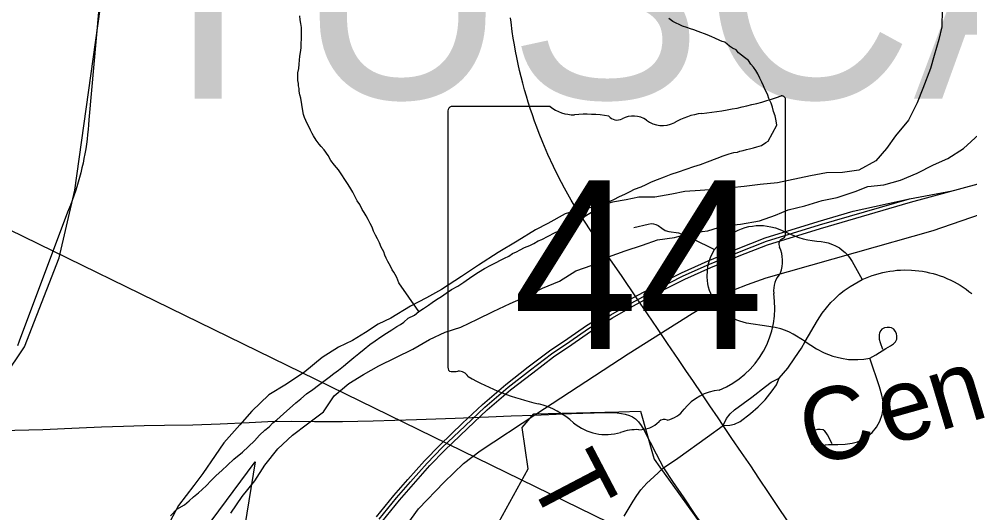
# Model space of a CAD drawing. Extents: x -6.1 to 38, y -7.7 to 22.
# Drawn here: x 5.97 to 6.713, y 18.842 to 19.227 of the extents above; entities that cross this region are included whole.
import ezdxf

# ---------------------------------------------------------------- set-up
doc = ezdxf.new("R2010")
doc.units = 0
for name, color, linetype in [('GM_X_City_Street', 7, 'Continuous'), ('GM_X_Corporation', 7, 'Continuous'), ('GM_X_County_Road', 7, 'Continuous'), ('GM_X_Major_River', 7, 'Continuous'), ('GM_X_Minor_River', 7, 'Continuous'), ('GM_X_Rail_Line', 7, 'Continuous'), ('GM_X_Rail_Line_Text', 7, 'Continuous'), ('GM_X_State_Location', 7, 'Continuous'), ('GM_X_State_Route', 7, 'Continuous'), ('GM_X_State_Shield', 7, 'Continuous'), ('GM_X_Township_Road', 7, 'Continuous'), ('GM_X_Township_Road_Text', 7, 'Continuous'), ('GM_X_Township_Text', 7, 'Continuous'), ('SH_Text', 7, 'Continuous')]:
    doc.layers.add(name, color=color, linetype=linetype)

msp = doc.modelspace()

# ---------------------------------------------------------------- linework, layer by layer
at = {"layer": 'GM_X_City_Street'}
for points in [[(6.45065, 19.06454), (6.46175, 19.06721), (6.46394, 19.06761), (6.4658, 19.06745), (6.46774, 19.06697), (6.4696, 19.06623), (6.47245, 19.064), (6.47502, 19.06227), (6.47785, 19.0613), (6.48538, 19.06042), (6.48829, 19.05944), (6.49598, 19.05588), (6.51351, 19.04728)], [(6.58441, 18.97548), (6.57768, 18.97978), (6.57498, 18.98132), (6.57219, 18.98271), (6.5691, 18.98403), (6.56543, 18.98532), (6.5609, 18.9864), (6.55596, 18.98716), (6.53845, 18.9899), (6.53585, 18.9905), (6.53334, 18.99127), (6.53087, 18.99222), (6.52846, 18.99335), (6.52562, 18.99497), (6.52339, 18.99645), (6.5213, 18.99809), (6.51937, 18.99985), (6.51752, 19.00176), (6.51581, 19.00378), (6.51425, 19.00593), (6.51288, 19.00817), (6.5116, 19.01051), (6.51056, 19.01293), (6.50966, 19.01541), (6.5089, 19.01796), (6.50839, 19.02054), (6.50801, 19.02317), (6.50781, 19.0258), (6.50801, 19.03109), (6.50839, 19.03371), (6.50891, 19.03629), (6.50967, 19.03884), (6.51077, 19.04177), (6.51351, 19.04728), (6.51746, 19.05175), (6.51946, 19.05389), (6.52154, 19.05587), (6.52439, 19.05814), (6.5268, 19.05976), (6.52936, 19.06121), (6.53197, 19.06249), (6.53467, 19.06358), (6.53742, 19.06448), (6.54026, 19.06519), (6.54311, 19.06569), (6.546, 19.06599), (6.54894, 19.0661), (6.55183, 19.06599), (6.55471, 19.06568), (6.5576, 19.06518), (6.56111, 19.06426), (6.56452, 19.06306), (6.57281, 19.05939), (6.57613, 19.05803), (6.57949, 19.05683), (6.5829, 19.05581), (6.58636, 19.05498), (6.58987, 19.05433), (6.59342, 19.05385), (6.59692, 19.05355), (6.59967, 19.05313), (6.60242, 19.05247), (6.60559, 19.05138), (6.60815, 19.05022), (6.61109, 19.04854), (6.61336, 19.0469), (6.61554, 19.04507), (6.61748, 19.04307), (6.61961, 19.04045), (6.62118, 19.0381), (6.62886, 19.02384)], [(6.5641, 18.94691), (6.57077, 18.9547), (6.57636, 18.96262), (6.58142, 18.97029), (6.58441, 18.97548), (6.59397, 18.99202), (6.59767, 18.99755), (6.60101, 19.00176), (6.60449, 19.0059), (6.60727, 19.00868), (6.6111, 19.01237), (6.61481, 19.01534), (6.61708, 19.017), (6.61945, 19.01858), (6.62886, 19.02384), (6.63413, 19.02612), (6.63679, 19.02708), (6.63948, 19.02794), (6.64223, 19.02871), (6.64503, 19.02939), (6.64758, 19.02993), (6.65038, 19.03041), (6.65323, 19.0308), (6.65607, 19.03109), (6.65891, 19.03128), (6.66176, 19.03137), (6.66744, 19.03126), (6.67023, 19.03105), (6.67308, 19.03075), (6.67592, 19.03035), (6.67872, 19.02984), (6.68146, 19.02925), (6.68426, 19.02855), (6.68696, 19.02776), (6.68966, 19.02687), (6.69236, 19.02589), (6.69496, 19.02483), (6.69814, 19.0234), (6.7006, 19.02215), (6.70307, 19.02082), (6.70543, 19.0194), (6.7078, 19.01791), (6.71008, 19.01633), (6.7123, 19.01467), (6.71448, 19.01294)], [(6.58441, 18.97548), (6.59321, 18.96968), (6.59925, 18.96652), (6.60602, 18.96392), (6.61263, 18.96234), (6.61824, 18.96148), (6.62541, 18.96139), (6.63021, 18.96179), (6.63484, 18.96259), (6.63946, 18.96509), (6.64723, 18.96999), (6.65106, 18.97211), (6.65341, 18.97358), (6.65495, 18.97513), (6.65582, 18.97735), (6.656, 18.97969), (6.65563, 18.9817), (6.65476, 18.98363), (6.6536, 18.98508), (6.65186, 18.98604), (6.65031, 18.98644), (6.64828, 18.98653), (6.6462, 18.98608), (6.64423, 18.98517), (6.64332, 18.98411), (6.64239, 18.98238), (6.6421, 18.98061), (6.64225, 18.97743), (6.64301, 18.97469), (6.64473, 18.96953)], [(6.60531, 18.89566), (6.60175, 18.90269), (6.60085, 18.9041), (6.5996, 18.90546), (6.59829, 18.90637), (6.59618, 18.90676), (6.59404, 18.90666), (6.59216, 18.90611), (6.59065, 18.90492), (6.58922, 18.90328), (6.58843, 18.90115), (6.58836, 18.89931), (6.58868, 18.89731), (6.58949, 18.89565), (6.59074, 18.89453), (6.59238, 18.89361), (6.59422, 18.89317), (6.59801, 18.89386), (6.60031, 18.8947), (6.60259, 18.89508), (6.60993, 18.89496), (6.61563, 18.89521), (6.62103, 18.89596), (6.62534, 18.89715), (6.62912, 18.89887), (6.633, 18.90125), (6.63667, 18.90438), (6.64012, 18.90858), (6.64271, 18.91322), (6.64454, 18.9184), (6.6453, 18.92304), (6.6454, 18.92649), (6.64498, 18.93005), (6.64411, 18.93361), (6.64238, 18.93998), (6.63484, 18.96259)], [(6.52032, 18.90992), (6.52549, 18.91002), (6.52919, 18.911), (6.53348, 18.91304), (6.54167, 18.91924), (6.54765, 18.92457), (6.55311, 18.92998), (6.55869, 18.93703), (6.56195, 18.94165), (6.5641, 18.94691)], [(6.52032, 18.90992), (6.52286, 18.91528), (6.52568, 18.91908), (6.52919, 18.92201), (6.54256, 18.93212), (6.55324, 18.94024), (6.55777, 18.9436), (6.5641, 18.94691)]]:
    msp.add_lwpolyline(points, dxfattribs=at)
at = {"layer": 'GM_X_Corporation'}
for points in [[(6.05133, 19.44458), (6.02484, 19.14859), (6.0246, 19.1448), (6.02431, 19.14102), (6.02393, 19.13724), (6.0235, 19.13348), (6.02298, 19.12971), (6.02241, 19.12595), (6.02179, 19.12221), (6.02108, 19.11848), (6.02032, 19.11476), (6.01951, 19.11107), (6.01861, 19.10737), (6.01766, 19.1037), (6.01662, 19.10005), (6.01552, 19.0964), (6.01439, 19.09279), (6.0132, 19.08919), (6.01192, 19.08562), (6.01059, 19.08206), (6.00831, 19.0765), (5.9704, 18.97578), (5.96908, 18.97223)], [(5.93858, 18.81896), (5.97794, 18.81995), (6.34227, 18.82912), (6.36798, 18.87608), (6.36335, 18.90837), (6.37231, 18.91892), (6.43888, 18.92061), (6.4557, 18.92104), (6.46568, 18.88615), (6.46644, 18.88349), (6.47084, 18.87738), (6.48566, 18.85674), (6.62273, 18.66603), (6.658, 18.6169), (6.66307, 18.60986), (6.66889, 18.60176), (6.66908, 18.60068), (6.67187, 18.58221), (6.67352, 18.57001), (6.68778, 18.46834), (6.69665, 18.40504), (7.00648, 18.41584)], [(6.08072, 18.78188), (6.15483, 18.88149), (6.13494, 18.75951)]]:
    msp.add_lwpolyline(points, dxfattribs=at)
at = {"layer": 'GM_X_County_Road'}
for points in [[(6.47378, 18.87668), (6.48491, 18.88443), (6.50803, 18.90105), (6.52032, 18.90992)], [(6.44301, 18.83916), (6.45004, 18.85081), (6.45274, 18.85512), (6.45587, 18.85952), (6.46078, 18.86476), (6.4661, 18.86975), (6.47378, 18.87668)]]:
    msp.add_lwpolyline(points, dxfattribs=at)
at = {"layer": 'GM_X_Major_River'}
for points in [[(6.69132, 19.23493), (6.69103, 19.22128), (6.68883, 19.21141), (6.68513, 19.19887), (6.68217, 19.18861), (6.67622, 19.17303), (6.67175, 19.162), (6.66503, 19.1483), (6.6549, 19.1361), (6.64778, 19.1262), (6.63952, 19.11666), (6.62633, 19.10937), (6.61349, 19.10739), (6.60101, 19.10731), (6.58854, 19.10495), (6.56286, 19.09947), (6.54925, 19.09825), (6.53679, 19.09665), (6.52658, 19.09544), (6.51335, 19.09422), (6.50239, 19.09339), (6.49029, 19.09255), (6.48009, 19.09059), (6.46687, 19.08823), (6.45439, 19.08814), (6.44457, 19.08618), (6.43399, 19.08422), (6.41965, 19.08033), (6.40718, 19.07835), (6.39699, 19.07525), (6.38343, 19.06758), (6.37362, 19.06259), (6.35931, 19.05377), (6.34462, 19.04495), (6.32918, 19.03499), (6.316, 19.02618), (6.30018, 19.01622), (6.2885, 19.0097), (6.27606, 19.00317), (6.26061, 18.99359), (6.25081, 18.98897), (6.24102, 18.98246), (6.23085, 18.97633), (6.21992, 18.97095), (6.20711, 18.9629), (6.19357, 18.95181), (6.17926, 18.94224), (6.16532, 18.9338), (6.15217, 18.9212), (6.14278, 18.91052), (6.13039, 18.89641), (6.12365, 18.88651), (6.11391, 18.87241), (6.10679, 18.86288), (6.09478, 18.84726), (6.08843, 18.83508)], [(6.13567, 18.84146), (6.14466, 18.85441), (6.15441, 18.86661), (6.16228, 18.8788), (6.1724, 18.89176), (6.18406, 18.90245), (6.19572, 18.91125), (6.20814, 18.92043), (6.21638, 18.933), (6.22804, 18.94256), (6.23934, 18.94984), (6.2514, 18.95636), (6.27779, 18.96943), (6.29098, 18.9771), (6.30304, 18.98287), (6.3155, 18.98674), (6.32832, 18.99289), (6.34076, 18.99904), (6.35395, 19.0052), (6.3664, 19.01059), (6.37922, 19.01712), (6.39242, 19.02252), (6.40522, 19.03056), (6.41805, 19.0352), (6.43087, 19.04173), (6.4437, 19.04636), (6.45728, 19.05062), (6.46898, 19.05487), (6.4822, 19.05685), (6.49504, 19.06035), (6.50827, 19.06196), (6.52072, 19.06583), (6.53395, 19.06705), (6.54868, 19.0698), (6.56114, 19.07406), (6.57094, 19.07829), (6.58416, 19.08141), (6.59775, 19.08567), (6.60946, 19.08803), (6.62342, 19.09267), (6.63323, 19.09652), (6.6457, 19.09774), (6.65891, 19.10162), (6.67173, 19.10701), (6.68455, 19.11354), (6.69586, 19.11855), (6.70791, 19.12621), (6.71995, 19.13728)], [(6.52043, 19.12057), (6.52496, 19.12217), (6.52875, 19.123), (6.5314, 19.12343), (6.53328, 19.12422), (6.53593, 19.12465), (6.53858, 19.12546), (6.54085, 19.12588), (6.54387, 19.12669), (6.54651, 19.1275), (6.55029, 19.12871), (6.55367, 19.13105), (6.55555, 19.13185)], [(6.09957, 18.84797), (6.10332, 18.85108), (6.10668, 18.85418), (6.11042, 18.85729), (6.11341, 18.86001), (6.11677, 18.86311), (6.12013, 18.86659), (6.12423, 18.87085), (6.12872, 18.87473), (6.1332, 18.87899), (6.13805, 18.88364), (6.14479, 18.88909), (6.14965, 18.89336), (6.15413, 18.898), (6.15823, 18.90226), (6.16234, 18.90614), (6.16571, 18.90886), (6.16869, 18.91196), (6.17168, 18.91429), (6.1743, 18.91662), (6.17692, 18.91895), (6.18664, 18.92749), (6.19038, 18.9306), (6.19487, 18.93448), (6.19974, 18.93799), (6.20424, 18.94149), (6.20836, 18.94461), (6.21248, 18.94772), (6.21623, 18.95046), (6.21998, 18.95319), (6.22372, 18.95629), (6.22709, 18.95902), (6.23196, 18.96291), (6.2357, 18.96602), (6.23982, 18.96951), (6.24431, 18.97302), (6.24843, 18.97613), (6.25293, 18.97926), (6.25744, 18.982), (6.26157, 18.98473), (6.26533, 18.98708), (6.26834, 18.98866), (6.27096, 18.99061), (6.27432, 18.99371), (6.27922, 18.99608), (6.28259, 18.9988), (6.28634, 19.00115), (6.29009, 19.00388), (6.2931, 19.00583), (6.29647, 19.00818), (6.30023, 19.01053), (6.30398, 19.01326), (6.30811, 19.01599), (6.31299, 19.01874), (6.31787, 19.02187), (6.32387, 19.02616), (6.32913, 19.02968), (6.33402, 19.03243), (6.3389, 19.03518), (6.34305, 19.03715), (6.34643, 19.03912), (6.34944, 19.04069), (6.35283, 19.04227), (6.35583, 19.04423), (6.35885, 19.04542), (6.36186, 19.047), (6.36524, 19.04896), (6.36939, 19.05055), (6.3724, 19.05213), (6.37578, 19.05409), (6.3788, 19.05529), (6.38858, 19.0604), (6.39197, 19.06199), (6.39498, 19.06356), (6.39762, 19.06475), (6.39988, 19.06593), (6.40364, 19.0679), (6.4074, 19.07025), (6.41153, 19.07299), (6.41604, 19.07573), (6.42092, 19.07848), (6.42581, 19.08123), (6.43031, 19.08435), (6.43483, 19.08633), (6.43935, 19.0887), (6.44349, 19.09067), (6.44763, 19.09265), (6.45102, 19.09461), (6.45631, 19.09622), (6.46007, 19.09819), (6.46421, 19.10017), (6.46911, 19.10216), (6.47439, 19.10415), (6.47968, 19.10615), (6.48534, 19.10815), (6.49138, 19.11016), (6.49742, 19.11217), (6.5027, 19.11379), (6.50799, 19.11578), (6.51553, 19.11858), (6.52043, 19.12057)], [(6.08871, 18.83941), (6.09356, 18.84444), (6.09957, 18.84797)]]:
    msp.add_lwpolyline(points, dxfattribs=at)
at = {"layer": 'GM_X_Minor_River'}
for points in [[(6.28259, 18.9988), (6.26699, 19.02134), (6.2654, 19.02549), (6.26422, 19.02775), (6.26304, 19.02963), (6.26187, 19.03151), (6.26069, 19.03377), (6.25951, 19.03604), (6.25834, 19.03791), (6.25715, 19.04055), (6.25597, 19.04282), (6.25517, 19.04546), (6.2532, 19.04923), (6.252, 19.05263), (6.25043, 19.05565), (6.24885, 19.05866), (6.24728, 19.06167), (6.24608, 19.06469), (6.24451, 19.06771), (6.24294, 19.07072), (6.24136, 19.07374), (6.2398, 19.07637), (6.23824, 19.07862), (6.23665, 19.0824), (6.23432, 19.0854), (6.23275, 19.08841), (6.23116, 19.09219), (6.22881, 19.09595), (6.22686, 19.09896), (6.22491, 19.10196), (6.22256, 19.10572), (6.21983, 19.10948), (6.21673, 19.11322), (6.214, 19.11698), (6.21166, 19.12074), (6.20854, 19.12525), (6.20621, 19.12787), (6.20466, 19.12974), (6.20232, 19.13274), (6.20036, 19.13613), (6.19919, 19.13801), (6.198, 19.14065), (6.19683, 19.14291), (6.19565, 19.14517), (6.19445, 19.14819), (6.19327, 19.15045), (6.19247, 19.15272), (6.19204, 19.15575), (6.19034, 19.16561), (6.18954, 19.16826), (6.18911, 19.17091), (6.18907, 19.17319), (6.18865, 19.17509), (6.18862, 19.17699), (6.1882, 19.17926), (6.18813, 19.18306), (6.18809, 19.18534), (6.18879, 19.18878), (6.18911, 19.19221), (6.18943, 19.19526), (6.18975, 19.1983), (6.19008, 19.20135), (6.19078, 19.20479), (6.19072, 19.20821), (6.19103, 19.21202), (6.19097, 19.21506), (6.19092, 19.2181), (6.19087, 19.22076), (6.19044, 19.22379), (6.19, 19.22683), (6.18957, 19.22986)], [(6.55555, 19.13185), (6.56216, 19.14451), (6.56172, 19.14793), (6.56089, 19.15172), (6.55969, 19.15512), (6.55887, 19.15853), (6.55768, 19.16155), (6.55609, 19.16532), (6.55528, 19.16797), (6.55411, 19.17023), (6.55292, 19.17249), (6.55174, 19.17513), (6.55054, 19.17815), (6.54897, 19.18116), (6.54739, 19.18456), (6.54582, 19.18719), (6.54388, 19.18982), (6.54194, 19.19207), (6.53998, 19.19508), (6.53691, 19.1973), (6.5346, 19.19916), (6.53228, 19.20102), (6.53034, 19.20327), (6.52766, 19.20474), (6.52535, 19.20622), (6.52343, 19.20771), (6.5215, 19.20919), (6.51959, 19.20992), (6.51768, 19.21065), (6.51385, 19.21248), (6.51155, 19.21358), (6.50964, 19.2143), (6.50772, 19.21503), (6.50084, 19.21757), (6.4974, 19.21903), (6.49473, 19.21974), (6.49205, 19.22083), (6.48861, 19.22191), (6.48593, 19.22301), (6.48364, 19.22411), (6.48095, 19.22558), (6.47787, 19.22781)]]:
    msp.add_lwpolyline(points, dxfattribs=at)
at = {"layer": 'GM_X_Rail_Line'}
msp.add_line((6.6659, 19.08696), (6.69916, 19.09305), dxfattribs=at)
for points in [[(4.164, 17.08105), (4.22288, 17.11422), (4.28514, 17.16362), (4.3773, 17.2385), (4.46626, 17.31066), (4.52352, 17.37506), (4.57967, 17.45347), (4.643, 17.54537), (5.03778, 18.11028), (5.18813, 18.32179), (5.2285, 18.37664), (5.2671, 18.40903), (5.31379, 18.44323), (5.44065, 18.5342), (5.77322, 18.77518), (5.85708, 18.83753), (5.92575, 18.89871), (5.97472, 18.97128), (6.00159, 19.04095), (6.01392, 19.09362), (6.04108, 19.2873)], [(6.25392, 18.83493), (6.26743, 18.8515), (6.27836, 18.86407), (6.29129, 18.87852), (6.30292, 18.89062), (6.32066, 18.90754), (6.33605, 18.92199), (6.35427, 18.93762), (6.37154, 18.95113), (6.38787, 18.96347), (6.40209, 18.97322), (6.41678, 18.98321), (6.43393, 18.9939), (6.44979, 19.00307), (6.46847, 19.01317), (6.49033, 19.0241), (6.51077, 19.03327), (6.53275, 19.04231), (6.55501, 19.05111), (6.59625, 19.06383), (6.66667, 19.08423), (6.7474, 19.10615)], [(6.24942, 18.8384), (6.26307, 18.85514), (6.27408, 18.86781), (6.2871, 18.88237), (6.29889, 18.89464), (6.31674, 18.91166), (6.33224, 18.92621), (6.35065, 18.94201), (6.36806, 18.95563), (6.38453, 18.96807), (6.39887, 18.9779), (6.41366, 18.98796), (6.43099, 18.99876), (6.447, 19.00802), (6.46584, 19.0182), (6.48788, 19.02923), (6.50852, 19.03848), (6.53061, 19.04757), (6.55312, 19.05646), (6.59462, 19.06926), (6.6219, 19.07717), (6.6659, 19.08696)], [(6.25167, 18.83667), (6.26525, 18.85332), (6.27622, 18.86594), (6.28919, 18.88045), (6.3009, 18.89263), (6.3187, 18.9096), (6.33415, 18.9241), (6.35246, 18.93981), (6.3698, 18.95338), (6.3862, 18.96577), (6.40048, 18.97556), (6.41522, 18.98559), (6.43246, 18.99633), (6.4484, 19.00554), (6.46716, 19.01569), (6.48911, 19.02666), (6.50965, 19.03587), (6.53168, 19.04494), (6.55407, 19.05378), (6.59544, 19.06655), (6.6659, 19.08696)], [(6.26379, 18.81929), (6.28238, 18.84483), (6.30238, 18.8657), (6.31752, 18.88007), (6.33043, 18.89016), (6.37391, 18.9187), (6.44622, 18.96597), (6.49602, 18.99732), (6.51776, 19.01042), (6.52873, 19.01576), (6.53931, 19.02013), (6.55387, 19.02528), (6.62375, 19.04498), (6.68442, 19.06216), (6.75906, 19.08788)]]:
    msp.add_lwpolyline(points, dxfattribs=at)
at = {"layer": 'GM_X_State_Route'}
msp.add_lwpolyline([(6.57235, 18.83268), (6.56515, 18.84345), (6.55615, 18.85688), (6.54826, 18.86868), (6.5418, 18.87832), (6.53461, 18.88889), (6.52718, 18.89984), (6.52032, 18.90992), (6.51633, 18.91579), (6.5099, 18.92526), (6.50363, 18.93448), (6.49703, 18.94421), (6.49109, 18.95295), (6.48536, 18.96138), (6.47686, 18.97388), (6.46891, 18.98558), (6.46112, 18.99706), (6.45262, 19.00956), (6.44083, 19.02692), (6.42695, 19.0472), (6.41926, 19.0583), (6.413, 19.06786), (6.40685, 19.07742), (6.40168, 19.08599), (6.3963, 19.09533), (6.39168, 19.10401), (6.38773, 19.11213), (6.38333, 19.12169), (6.37949, 19.13081), (6.37656, 19.13801), (6.37476, 19.14282), (6.37296, 19.14766), (6.37126, 19.15252), (6.36965, 19.15741), (6.36809, 19.16232), (6.36658, 19.16725), (6.36515, 19.1722), (6.36383, 19.17718), (6.36256, 19.18216), (6.36133, 19.18716), (6.36019, 19.1922), (6.35915, 19.19724), (6.35811, 19.20229), (6.35721, 19.20735), (6.35636, 19.21243), (6.35561, 19.21752), (6.35462, 19.22505), (6.35419, 19.22841)], dxfattribs=at)
at = {"layer": 'GM_X_State_Shield'}
for p, q in [((6.56901, 19.05927), (6.56901, 19.16396)), ((6.30535, 19.15555), (6.30535, 18.95543)), ((6.38516, 19.159), (6.30794, 19.159)), ((6.56899, 19.0593), (6.56901, 19.05927))]:
    msp.add_line(p, q, dxfattribs=at)
for centre, radius, start, end in [((6.47509, 19.43183), 0.27962, 275.84447, 288.90645), ((6.56609, 19.16439), 0.00294, 351.86209, 97.738), ((6.30837, 19.15598), 0.00305, 98.1301, 188.1301), ((6.40355, 19.18223), 0.02963, 231.61951, 271.11188), ((6.41337, 19.04665), 0.10636, 80.48669, 94.98827), ((6.43752, 19.15702), 0.00855, 219.79206, 297.10237), ((6.45007, 19.13389), 0.01777, 54.46668, 119.14113), ((6.473, 19.16561), 0.02138, 233.85621, 294.82819), ((6.51076, 19.09787), 0.05625, 97.34618, 120.76885), ((6.56588, 19.05887), 0.00314, 289.60381, 7.73413), ((6.56833, 19.05159), 0.00454, 107.94398, 210.33697), ((6.53944, 19.03835), 0.02727, 340.03296, 23.64957), ((6.57953, 19.01546), 0.01984, 136.8065, 186.92959), ((6.49075, 19.00214), 0.06994, 292.30889, 8.98584), ((6.30839, 18.95499), 0.00308, 171.95839, 258.30661), ((6.30886, 18.97547), 0.02352, 267.33899, 280.60386), ((6.31367, 18.94389), 0.00848, 29.74838, 93.27175), ((6.42073, 19.12369), 0.20192, 240.41292, 257.1985), ((6.52024, 18.89925), 0.0383, 94.40312, 142.57675), ((6.36053, 18.86553), 0.06318, 47.18416, 75.83597), ((6.47171, 18.93604), 0.0226, 282.87319, 323.27711), ((6.42886, 18.94289), 0.04009, 230.70037, 286.29184), ((6.45496, 18.92791), 0.02136, 268.77702, 315.54927), ((6.47428, 18.90853), 0.00601, 65.75173, 132.64842), ((6.45203, 18.8737), 0.03294, 85.69512, 111.20995)]:
    msp.add_arc(centre, radius, start, end, dxfattribs=at)
at = {"layer": 'GM_X_Township_Road'}
for points in [[(5.9285, 18.90563), (5.94702, 18.90579), (5.96702, 18.90621), (5.98887, 18.9068), (6.0173, 18.90799), (6.03468, 18.90872), (6.05205, 18.90944), (6.06798, 18.90975), (6.08392, 18.91005), (6.10601, 18.91047), (6.12744, 18.91113), (6.15004, 18.91213), (6.16462, 18.91288), (6.18297, 18.91321), (6.20106, 18.91297), (6.22299, 18.91288), (6.24683, 18.91347), (6.26381, 18.91403), (6.28079, 18.91459), (6.31087, 18.91555), (6.33696, 18.91672), (6.35463, 18.91734), (6.37229, 18.91797)], [(6.37229, 18.91797), (6.40186, 18.91915), (6.42832, 18.92003), (6.4376, 18.91987), (6.44094, 18.91937), (6.44383, 18.9187), (6.44727, 18.9177), (6.4496, 18.91661), (6.45194, 18.91503), (6.45411, 18.9127), (6.45613, 18.90999), (6.45828, 18.90653), (6.46798, 18.88783), (6.47378, 18.87668)], [(6.47378, 18.87668), (6.4807, 18.86617), (6.4895, 18.85329), (6.49829, 18.84041), (6.50835, 18.8262), (6.51841, 18.81199), (6.53663, 18.78684), (6.55486, 18.76169), (6.573, 18.73646), (6.58569, 18.71879), (6.59839, 18.70113), (6.61531, 18.67718), (6.61921, 18.67202), (6.62215, 18.66862)]]:
    msp.add_lwpolyline(points, dxfattribs=at)
at = {"layer": 'SH_Text'}
msp.add_lwpolyline([(5.44879, 19.3143), (6.62446, 18.73967), (5.44915, 18.64981)], close=True, dxfattribs=at)

# ---------------------------------------------------------------- texts
at = {"layer": 'GM_X_Rail_Line_Text'}
for s, rotation, p in [('n', 16.65341, (6.68892, 18.90537)), ('C', 16.20586, (6.58961, 18.87684)), ('e', 15.75547, (6.64867, 18.894))]:
    msp.add_text(s, height=0.05663, rotation=rotation, dxfattribs=at).set_placement(p)
at = {"layer": 'GM_X_State_Location'}
for s, p in [('s', (6.43421, 19.04219)), ('r', (6.4342, 19.04219))]:
    msp.add_text(s, height=0.000189, dxfattribs=at).set_placement(p)
msp.add_text('44', height=0.000189, rotation=0.00001, dxfattribs=at).set_placement((6.38652, 19.02841))
at = {"layer": 'GM_X_State_Shield'}
msp.add_text('44', height=0.131836, dxfattribs=at).set_placement((6.35593, 18.96954))
at = {"layer": 'GM_X_Township_Road_Text'}
msp.add_text('T', height=0.05682, rotation=297.67671, dxfattribs=at).set_placement((6.36694, 18.86931))
at = {"layer": 'GM_X_Township_Text'}
msp.add_text('TUSCARAWAS', height=0.170455, rotation=0.00001, dxfattribs=at).set_placement((6.04843, 19.16529))

doc.saveas('drawing.dxf')
